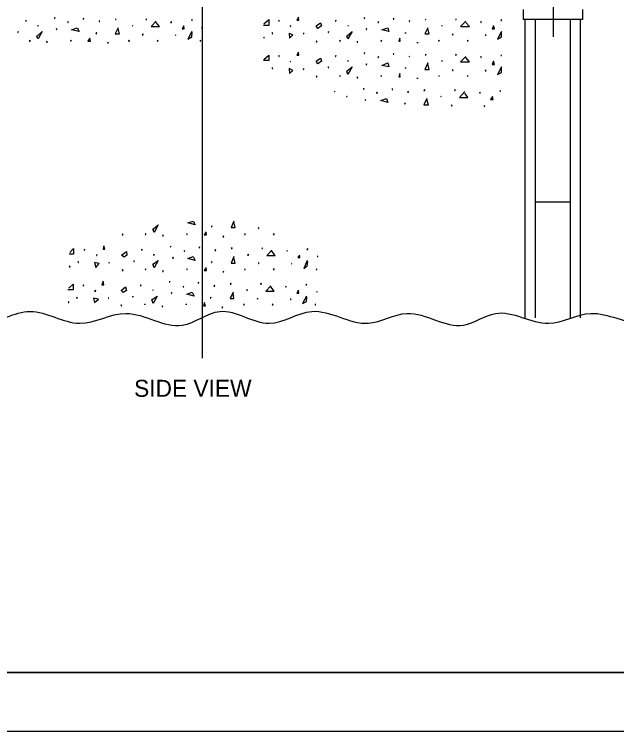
# Model space of a CAD drawing. Extents: x 637580 to 641008, y 294594 to 295782.
# Drawn here: x 637943.1 to 638095.4, y 294593.6 to 294775.2 of the extents above; entities that cross this region are included whole.
import ezdxf

# ---------------------------------------------------------------- set-up
doc = ezdxf.new("R2010")
doc.units = 0
for name, color, linetype in [('1', 7, 'Continuous'), ('2', 7, 'Continuous'), ('PLT-BNDY', 7, 'Continuous')]:
    doc.layers.add(name, color=color, linetype=linetype)

msp = doc.modelspace()

# ---------------------------------------------------------------- linework, layer by layer
at = {"layer": '1'}
for p, q in [((638406.31, 294608.63), (637620.31, 294608.63)), ((637620.31, 294608.63), (638206.31, 294608.63))]:
    msp.add_line(p, q, dxfattribs=at)
at = {"layer": '2'}
for p, q in [((638079.43, 294769.5), (638079.43, 294835.38)), ((637990.68, 294688.13), (637990.68, 294790.31)), ((638071.8, 294776.38), (638071.8, 294773.88)), ((638086.93, 294773.88), (638086.93, 294776.38)), ((638086.93, 294773.88), (638071.8, 294773.88)), ((638072.18, 294773.88), (638072.18, 294698.38)), ((638074.8, 294773.88), (638074.8, 294698.38)), ((638083.8, 294698.38), (638083.8, 294773.88)), ((638086.3, 294698.38), (638086.3, 294773.88)), ((638083.8, 294727.63), (638074.8, 294727.63))]:
    msp.add_line(p, q, dxfattribs=at)
for points in [[(637953.3, 294774.38), (637953.18, 294774.13), (637953.3, 294774.13), (637953.3, 294774.38)], [(637960.55, 294774.25), (637960.43, 294774), (637960.55, 294774), (637960.55, 294774.13)], [(637968.68, 294774), (637968.68, 294773.88), (637968.8, 294773.88), (637968.68, 294774)], [(637976.43, 294774), (637976.3, 294773.88), (637976.55, 294773.88), (637976.43, 294774)], [(638014.93, 294774.5), (638014.55, 294773.75), (638015.05, 294773.75), (638014.93, 294774.38)], [(638031.68, 294774.38), (638031.55, 294774.13), (638031.68, 294774.13), (638031.68, 294774.38)], [(638039.05, 294774.25), (638038.93, 294774), (638039.05, 294774), (638039.05, 294774.13)], [(638047.18, 294774), (638047.05, 294773.88), (638047.18, 294773.88), (638047.18, 294774)], [(638054.8, 294774), (638054.68, 294773.88), (638054.8, 294773.88), (638054.8, 294774)], [(637945.93, 294773.75), (637945.93, 294773.5), (637946.05, 294773.5), (637945.93, 294773.63)], [(637949.05, 294772.38), (637948.93, 294772.25), (637949.05, 294772.25), (637949.05, 294772.38)], [(637956.55, 294773.38), (637956.55, 294773.13), (637956.68, 294773.13), (637956.55, 294773.38)], [(637964.55, 294773.63), (637964.55, 294773.38), (637964.68, 294773.38), (637964.55, 294773.5)], [(637973.05, 294772.38), (637972.93, 294772.25), (637973.05, 294772.25), (637973.05, 294772.38)], [(637978.93, 294773.5), (637977.68, 294772.13), (637979.8, 294772.13), (637978.93, 294773.13)], [(637982.8, 294773.38), (637982.55, 294773.13), (637982.8, 294773.13), (637982.8, 294773.38)], [(637985.93, 294772.25), (637985.55, 294771.5), (637986.05, 294771.5), (637985.93, 294772.25)], [(637987.93, 294773.88), (637987.93, 294773.63), (637988.05, 294773.63), (637987.93, 294773.88)], [(638006.18, 294772.75), (638007.43, 294773.88), (638007.43, 294772.38), (638006.05, 294772.38)], [(638009.93, 294773.75), (638009.93, 294773.5), (638010.05, 294773.5), (638009.93, 294773.63)], [(638012.93, 294772.38), (638012.8, 294772.13), (638012.93, 294772.13), (638012.93, 294772.25)], [(638019.43, 294772.25), (638020.55, 294773), (638020.8, 294772.25), (638019.8, 294771.63), (638019.43, 294772.25)], [(638024.43, 294773.75), (638024.3, 294773.5), (638024.43, 294773.5), (638024.43, 294773.63)], [(638027.43, 294772.38), (638027.43, 294772.25), (638027.55, 294772.25), (638027.43, 294772.38)], [(638035.18, 294773.38), (638035.05, 294773.13), (638035.18, 294773.13), (638035.18, 294773.38)], [(638043.05, 294773.63), (638042.93, 294773.38), (638043.05, 294773.38), (638043.05, 294773.5)], [(638051.3, 294772.38), (638051.18, 294772.25), (638051.3, 294772.25), (638051.3, 294772.38)], [(638057.3, 294773.5), (638055.93, 294772.13), (638058.18, 294772.13), (638057.3, 294773.13)], [(638061.05, 294773.38), (638061.05, 294773.13), (638061.18, 294773.13), (638061.05, 294773.38)], [(638064.3, 294772.25), (638063.93, 294771.5), (638064.55, 294771.5), (638064.3, 294772.25)], [(638066.3, 294773.88), (638066.18, 294773.63), (638066.3, 294773.63), (638066.3, 294773.88)], [(637944.05, 294770.88), (637943.93, 294770.63), (637944.05, 294770.63), (637944.05, 294770.75)], [(637948.93, 294769.75), (637950.05, 294770.88), (637949.05, 294769), (637948.68, 294769.75)], [(637953.68, 294771.63), (637953.68, 294771.38), (637953.8, 294771.38), (637953.68, 294771.63)], [(637959.43, 294770.88), (637957.55, 294771.25), (637958.93, 294771.75), (637959.43, 294770.88)], [(637963.8, 294770.63), (637963.68, 294770.38), (637963.93, 294770.38), (637963.8, 294770.63)], [(637969.3, 294771.75), (637968.55, 294770.25), (637969.68, 294770.25), (637969.3, 294771.63)], [(637987.93, 294770.88), (637986.93, 294768.88), (637987.93, 294769.5), (637988.05, 294770.63)], [(637990.55, 294772), (637990.43, 294771.75), (637990.68, 294771.75), (637990.55, 294772)], [(638008.3, 294770.63), (638008.3, 294770.38), (638008.43, 294770.38), (638008.3, 294770.63)], [(638012.55, 294770.38), (638012.68, 294769.13), (638013.55, 294770), (638012.55, 294770.38)], [(638016.18, 294770.5), (638016.18, 294770.25), (638016.3, 294770.25), (638016.18, 294770.38)], [(638022.55, 294770.88), (638022.43, 294770.63), (638022.55, 294770.63), (638022.55, 294770.75)], [(638027.3, 294769.75), (638028.55, 294770.88), (638027.43, 294769), (638027.18, 294769.75)], [(638032.18, 294771.63), (638032.05, 294771.38), (638032.18, 294771.38), (638032.18, 294771.63)], [(638037.8, 294770.88), (638036.05, 294771.25), (638037.55, 294771.75), (638037.8, 294770.88)], [(638042.05, 294770.63), (638042.05, 294770.38), (638042.05, 294770.38), (638042.05, 294770.63)], [(638047.68, 294771.75), (638046.93, 294770.25), (638048.05, 294770.25), (638047.68, 294771.63)], [(638066.3, 294770.88), (638065.3, 294768.88), (638066.3, 294769.5), (638066.3, 294770.63)], [(637947.05, 294768.63), (637946.8, 294768.38), (637947.05, 294768.38), (637947.05, 294768.63)], [(637957.3, 294768.63), (637957.3, 294768.38), (637957.43, 294768.38), (637957.3, 294768.63)], [(637962.18, 294769.13), (637961.68, 294768.38), (637962.3, 294768.38), (637962.18, 294769.13)], [(637972.05, 294768.63), (637971.93, 294768.38), (637972.18, 294768.38), (637972.05, 294768.63)], [(637975.68, 294770.25), (637975.43, 294770), (637975.68, 294770), (637975.68, 294770.25)], [(637979.3, 294768.63), (637979.3, 294768.38), (637979.43, 294768.38), (637979.3, 294768.63)], [(637983.93, 294770), (637983.8, 294769.88), (637983.93, 294769.88), (637983.93, 294770)], [(637990.18, 294768.63), (637990.05, 294768.38), (637990.18, 294768.38), (637990.18, 294768.63)], [(638006.18, 294769.38), (638006.18, 294769.25), (638006.3, 294769.25), (638006.18, 294769.38)], [(638025.43, 294768.63), (638025.43, 294768.38), (638025.55, 294768.38), (638025.43, 294768.63)], [(638035.93, 294768.63), (638035.8, 294768.38), (638035.93, 294768.38), (638035.93, 294768.63)], [(638040.55, 294769.13), (638040.3, 294768.38), (638040.68, 294768.38), (638040.55, 294769.13)], [(638050.43, 294768.63), (638050.43, 294768.38), (638050.55, 294768.38), (638050.43, 294768.63)], [(638053.93, 294770.25), (638053.93, 294770), (638054.05, 294770), (638053.93, 294770.25)], [(638057.8, 294768.63), (638057.68, 294768.38), (638057.8, 294768.38), (638057.8, 294768.63)], [(638062.3, 294770), (638062.18, 294769.88), (638062.43, 294769.88), (638062.3, 294770)], [(637951.3, 294768.38), (637951.18, 294768.13), (637951.43, 294768.13), (637951.3, 294768.25)], [(637966.68, 294768.13), (637966.68, 294767.88), (637966.8, 294767.88), (637966.68, 294768.13)], [(638019.55, 294768.5), (638019.43, 294768.25), (638019.55, 294768.25), (638019.55, 294768.38)], [(638029.8, 294768.38), (638029.8, 294768.13), (638029.93, 294768.13), (638029.8, 294768.25)], [(638045.05, 294768.13), (638045.05, 294767.88), (638045.05, 294767.88), (638045.05, 294768.13)], [(638014.93, 294765.63), (638014.55, 294764.88), (638015.05, 294764.88), (638014.93, 294765.5)], [(638031.68, 294765.5), (638031.55, 294765.25), (638031.68, 294765.25), (638031.68, 294765.38)], [(638039.05, 294765.25), (638038.93, 294765.13), (638039.05, 294765.13), (638039.05, 294765.25)], [(638047.18, 294765.13), (638047.05, 294764.88), (638047.18, 294764.88), (638047.18, 294765.13)], [(638054.8, 294765.13), (638054.68, 294764.88), (638054.8, 294764.88), (638054.8, 294765.13)], [(638006.18, 294763.75), (638007.43, 294764.88), (638007.43, 294763.5), (638006.05, 294763.5)], [(638009.93, 294764.75), (638009.93, 294764.5), (638010.05, 294764.5), (638009.93, 294764.75)], [(638012.93, 294763.38), (638012.8, 294763.25), (638012.93, 294763.25), (638012.93, 294763.38)], [(638019.43, 294763.38), (638020.55, 294764.13), (638020.8, 294763.38), (638019.8, 294762.63), (638019.43, 294763.38)], [(638024.43, 294764.75), (638024.3, 294764.5), (638024.43, 294764.5), (638024.43, 294764.75)], [(638027.43, 294763.5), (638027.43, 294763.38), (638027.55, 294763.38), (638027.43, 294763.5)], [(638035.18, 294764.5), (638035.05, 294764.25), (638035.18, 294764.25), (638035.18, 294764.5)], [(638043.05, 294764.63), (638042.93, 294764.5), (638043.05, 294764.5), (638043.05, 294764.63)], [(638051.3, 294763.5), (638051.18, 294763.38), (638051.3, 294763.38), (638051.3, 294763.5)], [(638057.3, 294764.5), (638055.93, 294763.13), (638058.18, 294763.13), (638057.3, 294764.25)], [(638061.05, 294764.5), (638061.05, 294764.25), (638061.18, 294764.25), (638061.05, 294764.5)], [(638064.3, 294763.38), (638063.93, 294762.5), (638064.55, 294762.5), (638064.3, 294763.38)], [(638066.3, 294764.88), (638066.18, 294764.75), (638066.3, 294764.75), (638066.3, 294764.88)], [(638008.3, 294761.75), (638008.3, 294761.5), (638008.43, 294761.5), (638008.3, 294761.63)], [(638012.55, 294761.5), (638012.68, 294760.25), (638013.55, 294761), (638012.55, 294761.5)], [(638016.18, 294761.5), (638016.18, 294761.25), (638016.3, 294761.25), (638016.18, 294761.5)], [(638022.55, 294761.88), (638022.43, 294761.63), (638022.55, 294761.63), (638022.55, 294761.88)], [(638027.3, 294760.88), (638028.55, 294761.88), (638027.43, 294760), (638027.18, 294760.88)], [(638032.18, 294762.63), (638032.05, 294762.38), (638032.18, 294762.38), (638032.18, 294762.63)], [(638037.8, 294761.88), (638036.05, 294762.25), (638037.55, 294762.88), (638037.8, 294761.88)], [(638042.05, 294761.75), (638042.05, 294761.5), (638042.05, 294761.5), (638042.05, 294761.63)], [(638047.68, 294762.88), (638046.93, 294761.25), (638048.05, 294761.25), (638047.68, 294762.63)], [(638066.3, 294761.88), (638065.3, 294760), (638066.3, 294760.5), (638066.3, 294761.75)], [(638019.55, 294759.63), (638019.43, 294759.38), (638019.55, 294759.38), (638019.55, 294759.5)], [(638025.43, 294759.75), (638025.43, 294759.5), (638025.55, 294759.5), (638025.43, 294759.63)], [(638035.93, 294759.75), (638035.8, 294759.5), (638035.93, 294759.5), (638035.93, 294759.63)], [(638040.55, 294760.25), (638040.3, 294759.38), (638040.68, 294759.38), (638040.55, 294760.13)], [(638050.43, 294759.75), (638050.43, 294759.5), (638050.55, 294759.5), (638050.43, 294759.63)], [(638053.93, 294761.25), (638053.93, 294761), (638054.05, 294761), (638053.93, 294761.25)], [(638057.8, 294759.75), (638057.68, 294759.5), (638057.8, 294759.5), (638057.8, 294759.63)], [(638062.3, 294761.13), (638062.18, 294760.88), (638062.43, 294760.88), (638062.3, 294761)], [(638029.8, 294759.38), (638029.8, 294759.13), (638029.93, 294759.13), (638029.8, 294759.38)], [(638045.05, 294759.13), (638045.05, 294758.88), (638045.05, 294758.88), (638045.05, 294759.13)], [(638031.43, 294756.5), (638031.43, 294756.25), (638031.55, 294756.25), (638031.43, 294756.38)], [(638038.68, 294756.38), (638038.68, 294756.13), (638038.8, 294756.13), (638038.68, 294756.25)], [(638046.93, 294756.13), (638046.68, 294755.88), (638046.93, 294755.88), (638046.93, 294756.13)], [(638054.55, 294756.13), (638054.43, 294755.88), (638054.55, 294755.88), (638054.55, 294756.13)], [(638066.05, 294755.88), (638065.93, 294755.75), (638066.05, 294755.75), (638066.05, 294755.88)], [(638024.05, 294755.75), (638024.05, 294755.63), (638024.18, 294755.63), (638024.05, 294755.75)], [(638027.18, 294754.5), (638027.05, 294754.38), (638027.3, 294754.38), (638027.18, 294754.5)], [(638034.8, 294755.5), (638034.68, 294755.25), (638034.93, 294755.25), (638034.8, 294755.5)], [(638042.8, 294755.75), (638042.55, 294755.5), (638042.8, 294755.5), (638042.8, 294755.63)], [(638051.05, 294754.5), (638050.93, 294754.38), (638051.05, 294754.38), (638051.05, 294754.5)], [(638057.05, 294755.63), (638055.68, 294754.13), (638057.8, 294754.13), (638057.05, 294755.25)], [(638060.8, 294755.5), (638060.8, 294755.25), (638060.93, 294755.25), (638060.8, 294755.5)], [(638064.05, 294754.38), (638063.55, 294753.63), (638064.18, 294753.63), (638064.05, 294754.38)], [(638031.93, 294753.63), (638031.8, 294753.5), (638031.93, 294753.5), (638031.93, 294753.63)], [(638037.55, 294752.88), (638035.8, 294753.38), (638037.18, 294753.88), (638037.55, 294752.88)], [(638041.93, 294752.75), (638041.8, 294752.5), (638041.93, 294752.5), (638041.93, 294752.63)], [(638047.43, 294753.88), (638046.68, 294752.25), (638047.8, 294752.25), (638047.43, 294753.63)], [(638053.68, 294752.25), (638053.68, 294752), (638053.8, 294752), (638053.68, 294752.25)], [(638062.05, 294752.13), (638061.93, 294751.88), (638062.05, 294751.88), (638062.05, 294752.13)], [(637978.3, 294720.88), (637979.43, 294721.88), (637978.43, 294720), (637978.05, 294720.88)], [(637988.8, 294721.88), (637986.93, 294722.38), (637988.3, 294722.88), (637988.8, 294721.88)], [(637993.05, 294721.63), (637992.93, 294721.38), (637993.05, 294721.38), (637993.05, 294721.5)], [(637998.55, 294722.88), (637997.93, 294721.25), (637998.93, 294721.25), (637998.55, 294722.63)], [(637970.43, 294719.63), (637970.3, 294719.38), (637970.55, 294719.38), (637970.43, 294719.5)], [(637976.3, 294719.75), (637976.18, 294719.5), (637976.3, 294719.5), (637976.3, 294719.63)], [(637986.68, 294719.75), (637986.68, 294719.5), (637986.8, 294719.5), (637986.68, 294719.63)], [(637991.55, 294720.13), (637991.05, 294719.38), (637991.68, 294719.38), (637991.55, 294720)], [(638001.43, 294719.75), (638001.3, 294719.5), (638001.43, 294719.5), (638001.43, 294719.63)], [(638004.8, 294721.25), (638004.8, 294721), (638004.93, 294721), (638004.8, 294721.25)], [(638008.8, 294719.75), (638008.55, 294719.5), (638008.8, 294719.5), (638008.8, 294719.63)], [(637980.68, 294719.38), (637980.55, 294719.13), (637980.68, 294719.13), (637980.68, 294719.38)], [(637995.93, 294719.13), (637995.8, 294718.88), (637996.05, 294718.88), (637995.93, 294719.13)], [(637965.68, 294716.63), (637965.55, 294715.75), (637965.93, 294715.75), (637965.68, 294716.5)], [(637982.55, 294716.5), (637982.55, 294716.38), (637982.68, 294716.38), (637982.55, 294716.5)], [(637989.93, 294716.38), (637989.8, 294716.13), (637989.93, 294716.13), (637989.93, 294716.38)], [(637998.18, 294716.13), (637997.93, 294715.88), (637998.18, 294715.88), (637998.18, 294716.13)], [(638005.8, 294716.13), (638005.68, 294715.88), (638005.8, 294715.88), (638005.8, 294716.13)], [(637957.05, 294714.88), (637958.05, 294715.88), (637958.05, 294714.5), (637956.93, 294714.5)], [(637960.8, 294715.75), (637960.68, 294715.5), (637960.8, 294715.5), (637960.8, 294715.63)], [(637963.93, 294714.38), (637963.8, 294714.13), (637963.93, 294714.13), (637963.93, 294714.25)], [(637970.18, 294714.25), (637971.43, 294715.13), (637971.55, 294714.25), (637970.8, 294713.75), (637970.18, 294714.25)], [(637975.3, 294715.75), (637975.18, 294715.5), (637975.43, 294715.5), (637975.3, 294715.63)], [(637978.43, 294714.5), (637978.3, 294714.25), (637978.43, 294714.25), (637978.43, 294714.5)], [(637986.05, 294715.38), (637986.05, 294715.25), (637986.18, 294715.25), (637986.05, 294715.38)], [(637993.93, 294715.63), (637993.8, 294715.38), (637994.05, 294715.38), (637993.93, 294715.63)], [(638002.3, 294714.5), (638002.05, 294714.25), (638002.3, 294714.25), (638002.3, 294714.5)], [(638008.18, 294715.5), (638006.93, 294714.13), (638009.05, 294714.13), (638008.18, 294715.25)], [(638012.05, 294715.38), (638012.05, 294715.25), (638012.05, 294715.25), (638012.05, 294715.38)], [(638015.18, 294714.25), (638014.8, 294713.63), (638015.3, 294713.63), (638015.18, 294714.25)], [(638017.3, 294715.88), (638017.05, 294715.63), (638017.3, 294715.63), (638017.3, 294715.88)], [(637959.18, 294712.63), (637959.18, 294712.38), (637959.3, 294712.38), (637959.18, 294712.63)], [(637963.3, 294712.38), (637963.68, 294711.13), (637964.55, 294712.13), (637963.3, 294712.38)], [(637967.05, 294712.38), (637967.05, 294712.25), (637967.05, 294712.25), (637967.05, 294712.38)], [(637973.3, 294712.88), (637973.3, 294712.63), (637973.43, 294712.63), (637973.3, 294712.75)], [(637978.3, 294712), (637979.43, 294712.88), (637978.43, 294711), (637978.05, 294712)], [(637983.18, 294713.75), (637983.05, 294713.5), (637983.3, 294713.5), (637983.18, 294713.63)], [(637988.8, 294712.88), (637986.93, 294713.38), (637988.3, 294713.88), (637988.8, 294712.88)], [(637993.05, 294712.63), (637992.93, 294712.38), (637993.05, 294712.38), (637993.05, 294712.63)], [(637998.55, 294713.88), (637997.93, 294712.25), (637998.93, 294712.25), (637998.55, 294713.63)], [(638004.8, 294712.38), (638004.8, 294712.13), (638004.93, 294712.13), (638004.8, 294712.25)], [(638017.18, 294712.88), (638016.3, 294710.88), (638017.18, 294711.5), (638017.3, 294712.63)], [(638019.8, 294714), (638019.68, 294713.88), (638019.8, 294713.88), (638019.8, 294714)], [(637957.05, 294711.5), (637956.93, 294711.25), (637957.18, 294711.25), (637957.05, 294711.38)], [(637970.43, 294710.63), (637970.3, 294710.38), (637970.55, 294710.38), (637970.43, 294710.63)], [(637976.3, 294710.75), (637976.18, 294710.63), (637976.3, 294710.63), (637976.3, 294710.75)], [(637986.68, 294710.75), (637986.68, 294710.63), (637986.8, 294710.63), (637986.68, 294710.75)], [(637991.55, 294711.13), (637991.05, 294710.38), (637991.68, 294710.38), (637991.55, 294711)], [(638001.43, 294710.75), (638001.3, 294710.63), (638001.43, 294710.63), (638001.43, 294710.75)], [(638008.8, 294710.75), (638008.55, 294710.63), (638008.8, 294710.63), (638008.8, 294710.75)], [(638013.18, 294712.13), (638013.18, 294712), (638013.3, 294712), (638013.18, 294712.13)], [(638019.55, 294710.75), (638019.43, 294710.63), (638019.55, 294710.63), (638019.55, 294710.75)], [(637980.68, 294710.38), (637980.55, 294710.13), (637980.68, 294710.13), (637980.68, 294710.38)], [(637995.93, 294710.13), (637995.8, 294710), (637996.05, 294710), (637995.93, 294710.13)], [(637956.8, 294705.88), (637957.93, 294706.88), (637957.93, 294705.5), (637956.55, 294705.5)], [(637965.55, 294707.63), (637965.18, 294706.75), (637965.68, 294706.75), (637965.55, 294707.63)], [(637982.3, 294707.63), (637982.3, 294707.38), (637982.43, 294707.38), (637982.3, 294707.5)], [(637989.68, 294707.38), (637989.55, 294707.13), (637989.68, 294707.13), (637989.68, 294707.38)], [(637997.8, 294707.13), (637997.68, 294706.88), (637997.93, 294706.88), (637997.8, 294707.13)], [(638005.43, 294707.13), (638005.3, 294706.88), (638005.55, 294706.88), (638005.43, 294707.13)], [(638016.93, 294706.88), (638016.8, 294706.75), (638017.05, 294706.75), (638016.93, 294706.88)], [(637960.55, 294706.75), (637960.43, 294706.5), (637960.55, 294706.5), (637960.55, 294706.75)], [(637963.55, 294705.38), (637963.3, 294705.13), (637963.68, 294705.13), (637963.55, 294705.38)], [(637970.05, 294705.25), (637971.18, 294706.25), (637971.43, 294705.25), (637970.55, 294704.75), (637970.05, 294705.25)], [(637975.05, 294706.75), (637974.93, 294706.5), (637975.05, 294706.5), (637975.05, 294706.75)], [(637978.18, 294705.5), (637978.05, 294705.38), (637978.18, 294705.38), (637978.18, 294705.5)], [(637985.8, 294706.38), (637985.8, 294706.25), (637985.93, 294706.25), (637985.8, 294706.38)], [(637993.68, 294706.63), (637993.55, 294706.38), (637993.8, 294706.38), (637993.68, 294706.63)], [(638001.93, 294705.5), (638001.8, 294705.38), (638002.05, 294705.38), (638001.93, 294705.5)], [(638007.93, 294706.5), (638006.68, 294705.13), (638008.8, 294705.13), (638007.93, 294706.25)], [(638011.8, 294706.38), (638011.68, 294706.25), (638011.8, 294706.25), (638011.8, 294706.38)], [(638014.93, 294705.38), (638014.55, 294704.63), (638015.05, 294704.63), (638014.93, 294705.25)], [(638019.55, 294705), (638019.55, 294704.88), (638019.55, 294704.88), (638019.55, 294705)], [(637958.93, 294703.63), (637958.8, 294703.38), (637958.93, 294703.38), (637958.93, 294703.63)], [(637963.05, 294703.38), (637963.3, 294702.25), (637964.3, 294703.13), (637963.05, 294703.38)], [(637966.93, 294703.38), (637966.8, 294703.38), (637966.93, 294703.38), (637966.93, 294703.38)], [(637973.05, 294703.88), (637973.05, 294703.63), (637973.05, 294703.63), (637973.05, 294703.75)], [(637977.93, 294703), (637979.18, 294703.88), (637978.18, 294702), (637977.8, 294703)], [(637982.8, 294704.75), (637982.8, 294704.5), (637982.93, 294704.5), (637982.8, 294704.75)], [(637988.55, 294703.88), (637986.68, 294704.38), (637988.05, 294704.88), (637988.55, 294703.88)], [(637992.8, 294703.63), (637992.68, 294703.38), (637992.8, 294703.38), (637992.8, 294703.63)], [(637998.43, 294704.88), (637997.68, 294703.25), (637998.55, 294703.25), (637998.43, 294704.63)], [(638004.55, 294703.38), (638004.55, 294703.13), (638004.55, 294703.13), (638004.55, 294703.25)], [(638012.93, 294703.25), (638012.93, 294703), (638013.05, 294703), (638012.93, 294703.13)], [(638016.93, 294703.88), (638015.93, 294702), (638016.93, 294702.5), (638017.05, 294703.63)], [(637956.8, 294702.5), (637956.68, 294702.25), (637956.8, 294702.25), (637956.8, 294702.38)], [(637970.05, 294701.63), (637970.05, 294701.38), (637970.18, 294701.38), (637970.05, 294701.63)], [(637976.05, 294701.88), (637976.05, 294701.63), (637976.05, 294701.63), (637976.05, 294701.75)], [(637980.55, 294701.38), (637980.43, 294701.13), (637980.55, 294701.13), (637980.55, 294701.38)], [(637986.55, 294701.88), (637986.55, 294701.63), (637986.55, 294701.63), (637986.55, 294701.75)], [(637991.18, 294702.25), (637990.93, 294701.38), (637991.43, 294701.38), (637991.18, 294702)], [(638001.18, 294701.88), (638001.05, 294701.63), (638001.18, 294701.63), (638001.18, 294701.75)], [(638008.43, 294701.88), (638008.3, 294701.63), (638008.55, 294701.63), (638008.43, 294701.75)], [(638019.18, 294701.88), (638019.18, 294701.63), (638019.3, 294701.63), (638019.18, 294701.75)], [(637995.68, 294701.13), (637995.55, 294701), (637995.8, 294701), (637995.68, 294701.13)]]:
    msp.add_lwpolyline(points, dxfattribs=at)
msp.add_spline([(637860.55, 294697.38), (637873.43, 294700.75), (637882.43, 294696.5), (637895.3, 294699.5), (637907.93, 294696.5), (637922.43, 294699.5), (637935.05, 294697), (637947.05, 294700), (637959.55, 294697), (637971.3, 294699.5), (637985.55, 294696.5), (637995.05, 294700), (638007.55, 294697), (638018.3, 294700), (638032.55, 294697), (638042.43, 294699.5), (638056.68, 294696.5), (638064.8, 294699.5), (638078.18, 294697), (638088.93, 294699.5), (638102.05, 294697), (638112.8, 294699.5), (638127.05, 294696.5), (638136.55, 294699.5), (638150.3, 294696.5), (638158.43, 294700), (638170.18, 294696.5), (638184.43, 294698.63)], degree=3, dxfattribs=at)
at = {"layer": 'PLT-BNDY'}
msp.add_lwpolyline([(637580.31, 295187.63), (638421.31, 295187.63), (638421.31, 294593.63), (637580.31, 294593.63)], close=True, dxfattribs=at)

# ---------------------------------------------------------------- texts
at = {"layer": '2'}
msp.add_text('SIDE VIEW', height=4.3, dxfattribs=at).set_placement((637973.35, 294678.38))

doc.saveas('drawing.dxf')
